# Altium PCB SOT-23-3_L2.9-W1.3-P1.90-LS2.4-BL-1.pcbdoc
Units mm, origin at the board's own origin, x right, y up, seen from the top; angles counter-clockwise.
Board outline 15.75 x 15.95 mm, 2 copper layers (Top Layer, Bottom Layer), stack 0 mm thick; 1 components, 0 nets, 3 pads, 0 vias.
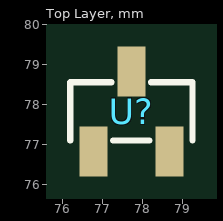
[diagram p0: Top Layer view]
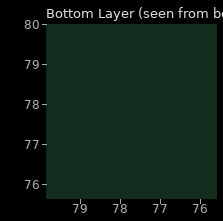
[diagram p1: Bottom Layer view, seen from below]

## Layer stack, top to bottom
Top Layer: signal copper (thickness not stored)
Bottom Layer: signal copper (thickness not stored)

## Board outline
85.603,69.85 69.85,69.85 69.85,85.8 85.603,85.8

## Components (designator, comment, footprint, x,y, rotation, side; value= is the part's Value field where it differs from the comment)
U? "" SOT-23-3_L2.9-W1.3-P1.90-LS2.4-BL-1 77.726,77.825 r0 top

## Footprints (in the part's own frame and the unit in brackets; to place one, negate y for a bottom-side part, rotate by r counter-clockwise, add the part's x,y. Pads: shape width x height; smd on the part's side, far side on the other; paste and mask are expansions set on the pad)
SOT-23-3_L2.9-W1.3-P1.90-LS2.4-BL-1 [mm]
  rect 0.7x1.25 smd: 1(-0.95,-1) 2(0.95,-1) 3(0,1)
  silkscreen extent -1.53,-0.73 1.53,0.73

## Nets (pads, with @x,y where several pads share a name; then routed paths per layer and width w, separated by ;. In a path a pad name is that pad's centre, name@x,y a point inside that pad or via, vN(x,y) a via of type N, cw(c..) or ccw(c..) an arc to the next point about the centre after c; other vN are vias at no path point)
pads on no net: U?.1 U?.2 U?.3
